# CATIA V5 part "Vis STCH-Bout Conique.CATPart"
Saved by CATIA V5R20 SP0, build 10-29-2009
Part number: Vis STHC-Conique M 4x4
Material "Acier": density 7860 kg/m3, Young's modulus 2e+11 Pa, Poisson ratio 0.266, thermal expansion 1.17e-05 1/K
Bounding box of the stored display mesh (mm): x -1.97 to 1.97, y -1.997 to 1.997, z 0 to 4
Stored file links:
  C:\travail\CAO\bib catia\vis\Vis STCH-Bout Conique.CATPart
  C:\Program Files\Dassault Systemes\B20\win_b64\startup\materials\French\Catalog.CATMaterial
  C:\Program Files\Dassault Systemes\B20\win_b64\reffiles\standard\MetricThickPitch.txt
  C:\travail\CAO\bib catia\vis\vis-HTSC_BP.xls
  C:\travail\CAO\bib catia\vis\vis-HTSC_BC.xls
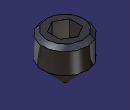
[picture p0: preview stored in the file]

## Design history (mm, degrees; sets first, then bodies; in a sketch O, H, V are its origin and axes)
Parameters
  d = 4 mm {design table}
  dp = 0.4 mm {design table}
  t = 2.5 mm {design table}
  s = 2 mm {design table}
  p = 0.7 mm {design table}
  l = 4 mm {design table}
  Designation = "Vis STHC-Conique M 4x4" {design table}
  dn = "M4" {design table}
Body1 (main body)
  Sketch1 on yz-plane, origin (0, 0, 0), H (0, 1, 0), V (0, 0, 1)
    axis line L1 (0, 0) -> (0, 10.0456)
    line L2 (0, 0) -> (-0.2, 0)
    point P2 (-0.2, 0)
    line L3 (-0.2, 0) -> (-2, 1.8)
    line L4 (-2, 1.8) -> (-2, 4)
    line L5 (-2, 4) -> (0, 4)
    point P5 (0, 4)
    line L6 (0, 4) -> (0, 0)
    "Radius" L4 L1 = 2 {= d /2}
    distance L2 L5 = 4 {= l}
    "Radius" P2 L1 = 0.2 {= dp /2}
    angle L2 L3 = 45
    vertical: L1 V, L4 V, L6 V
    horizontal: L2 H, L5 H
    coincidence: P5 L1
  Shaft1: profile Sketch1, axis Sketch1.L1, angle 360
  Thread1: "M4", diameter 4, depth 2.2, pitch 0.7, on face of Shaft1 from Sketch1.L4, from face of Shaft1 from Sketch1.L5
  Chamfer1: length 0.35 {= p /2}, angle 45, on edge [face of Shaft1 from Sketch1.L4 | face of Shaft1 from Sketch1.L5]
  Sketch2 on face of Shaft1 from Sketch1.L5, origin (0, 0, 4), H (1, 0, 0), V (0, 1, 0)
    point P1 (0, 0)
    point P2 (1, -0.5774)
    point P3 (1, 0.5774)
    point P4 (0, 1.1547)
    point P5 (-1, 0.5774)
    point P6 (-1, -0.5774)
    point P7 (0, -1.1547)
    point P8 (1, 0)
    line L1 (1, -0.5774) -> (1, 0.5774)
    line L2 (1, 0.5774) -> (0, 1.1547)
    line L3 (0, 1.1547) -> (-1, 0.5774)
    line L4 (-1, 0.5774) -> (-1, -0.5774)
    line L5 (-1, -0.5774) -> (0, -1.1547)
    line L6 (0, -1.1547) -> (1, -0.5774)
    construction line L7 (0, 0) -> (1, 0)
    construction circle A1 centre (0, 0) radius 1.1547
    construction arc A2 centre (-1, -0.5774) radius 1.1547 from (-1, 0.5774) to (0, -1.1547) cw
    construction arc A3 centre (1, 0.5774) radius 1.1547 from (0, 1.1547) to (1, -0.5774) ccw
    distance L4 L1 = 2 {= s}
    coincidence: P1 H, A1 P2, A1 P3, A1 P4, A1 P5, A1 P6, A1 P7, A2 P1, A3 P1, P1 O
    horizontal: L7 H
    midpoint: P8 L1
  Pocket1: profile Sketch2, direction (0, 0, -1), length 2.5 {= t}
Relations
  Thread1.ThreadDescription = dn
  design table, configuration 4, drives dn, d, p, dp, s, t, l, Designation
